// Mitsubishi GX Works2 project: FX3U MODBUS通信 发给客户   PLC: FX3U/FX3UC

PROGRAM MAIN
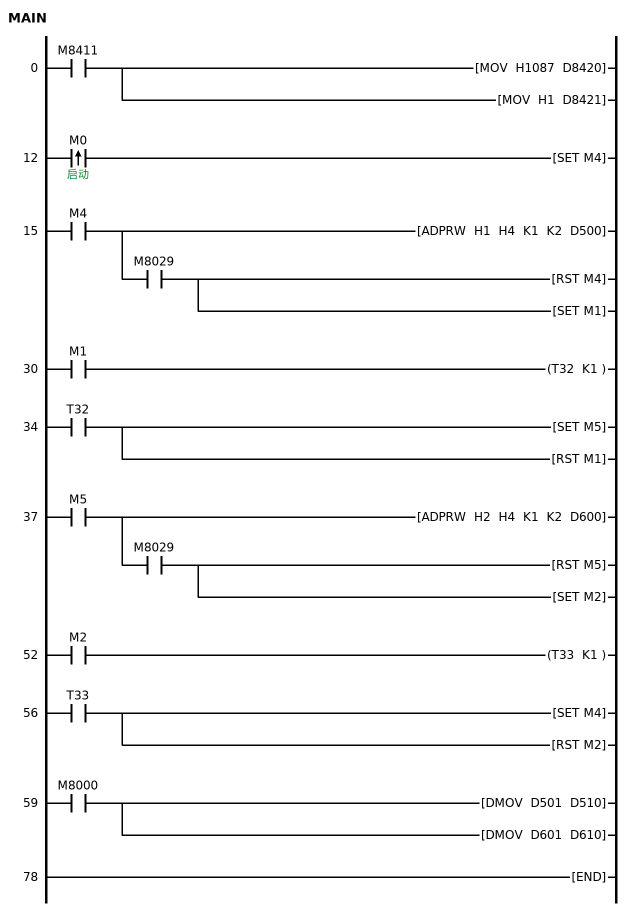
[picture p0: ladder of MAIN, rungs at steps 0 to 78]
0     LD      M8411
      MOV     H1087 D8420
      MOV     H1 D8421
12    LDP     M0  ; 启动
      SET     M4
15    LD      M4
      ADPRW   H1 H4 K1 K2 D500
      AND     M8029
      RST     M4
      SET     M1
30    LD      M1
      OUT     T32 K1
34    LD      T32
      SET     M5
      RST     M1
37    LD      M5
      ADPRW   H2 H4 K1 K2 D600
      AND     M8029
      RST     M5
      SET     M2
52    LD      M2
      OUT     T33 K1
56    LD      T33
      SET     M4
      RST     M2
59    LD      M8000
      DMOV    D501 D510
      DMOV    D601 D610
78    END
END_PROGRAM
